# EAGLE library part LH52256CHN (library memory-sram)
MEMORY
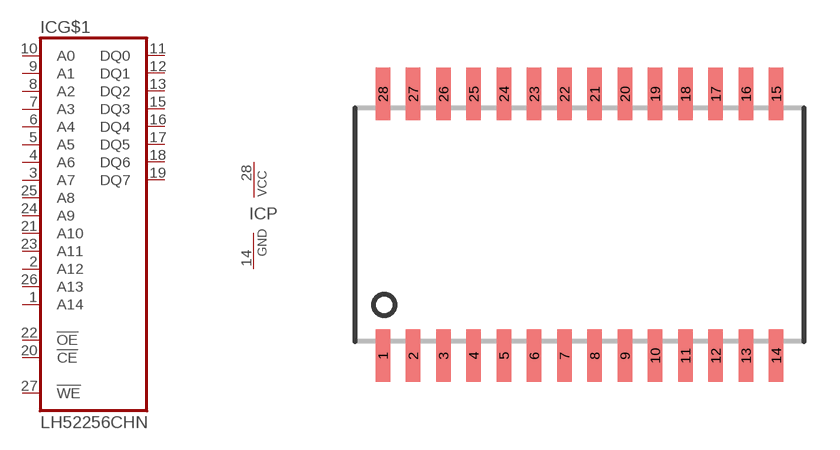
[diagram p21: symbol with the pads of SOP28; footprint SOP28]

Designator prefix IC; gates P=PWRN G$1=LH52256

## LH52256CHN  [SOP28]
1  G$1:A14  in
2  G$1:A12  in
3  G$1:A7  in
4  G$1:A6  in
5  G$1:A5  in
6  G$1:A4  in
7  G$1:A3  in
8  G$1:A2  in
9  G$1:A1  in
10  G$1:A0  in
11  G$1:DQ0
12  G$1:DQ1
13  G$1:DQ2
14  P:GND  pwr
15  G$1:DQ3
16  G$1:DQ4
17  G$1:DQ5
18  G$1:DQ6
19  G$1:DQ7
20  G$1:!CE  in
21  G$1:A10  in
22  G$1:!OE  in
23  G$1:A11  in
24  G$1:A9  in
25  G$1:A8  in
26  G$1:A13  in
27  G$1:!WE  in
28  P:VCC  pwr

## Footprint SOP28 (pad centres in mm)
Small Outline Package
smd 0.6 x 2.2: 1 -8.255,-5.5; 2 -6.985,-5.5; 3 -5.715,-5.5; 4 -4.445,-5.5; 5 -3.175,-5.5; 6 -1.905,-5.5; 7 -0.635,-5.5; 8 0.635,-5.5; 9 1.905,-5.5; 10 3.175,-5.5; 11 4.445,-5.5; 12 5.715,-5.5; 13 6.985,-5.5; 14 8.255,-5.5; 15 8.255,5.5; 16 6.985,5.5; 17 5.715,5.5; 18 4.445,5.5; 19 3.175,5.5; 20 1.905,5.5; 21 0.635,5.5; 22 -0.635,5.5; 23 -1.905,5.5; 24 -3.175,5.5; 25 -4.445,5.5; 26 -5.715,5.5; 27 -6.985,5.5; 28 -8.255,5.5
